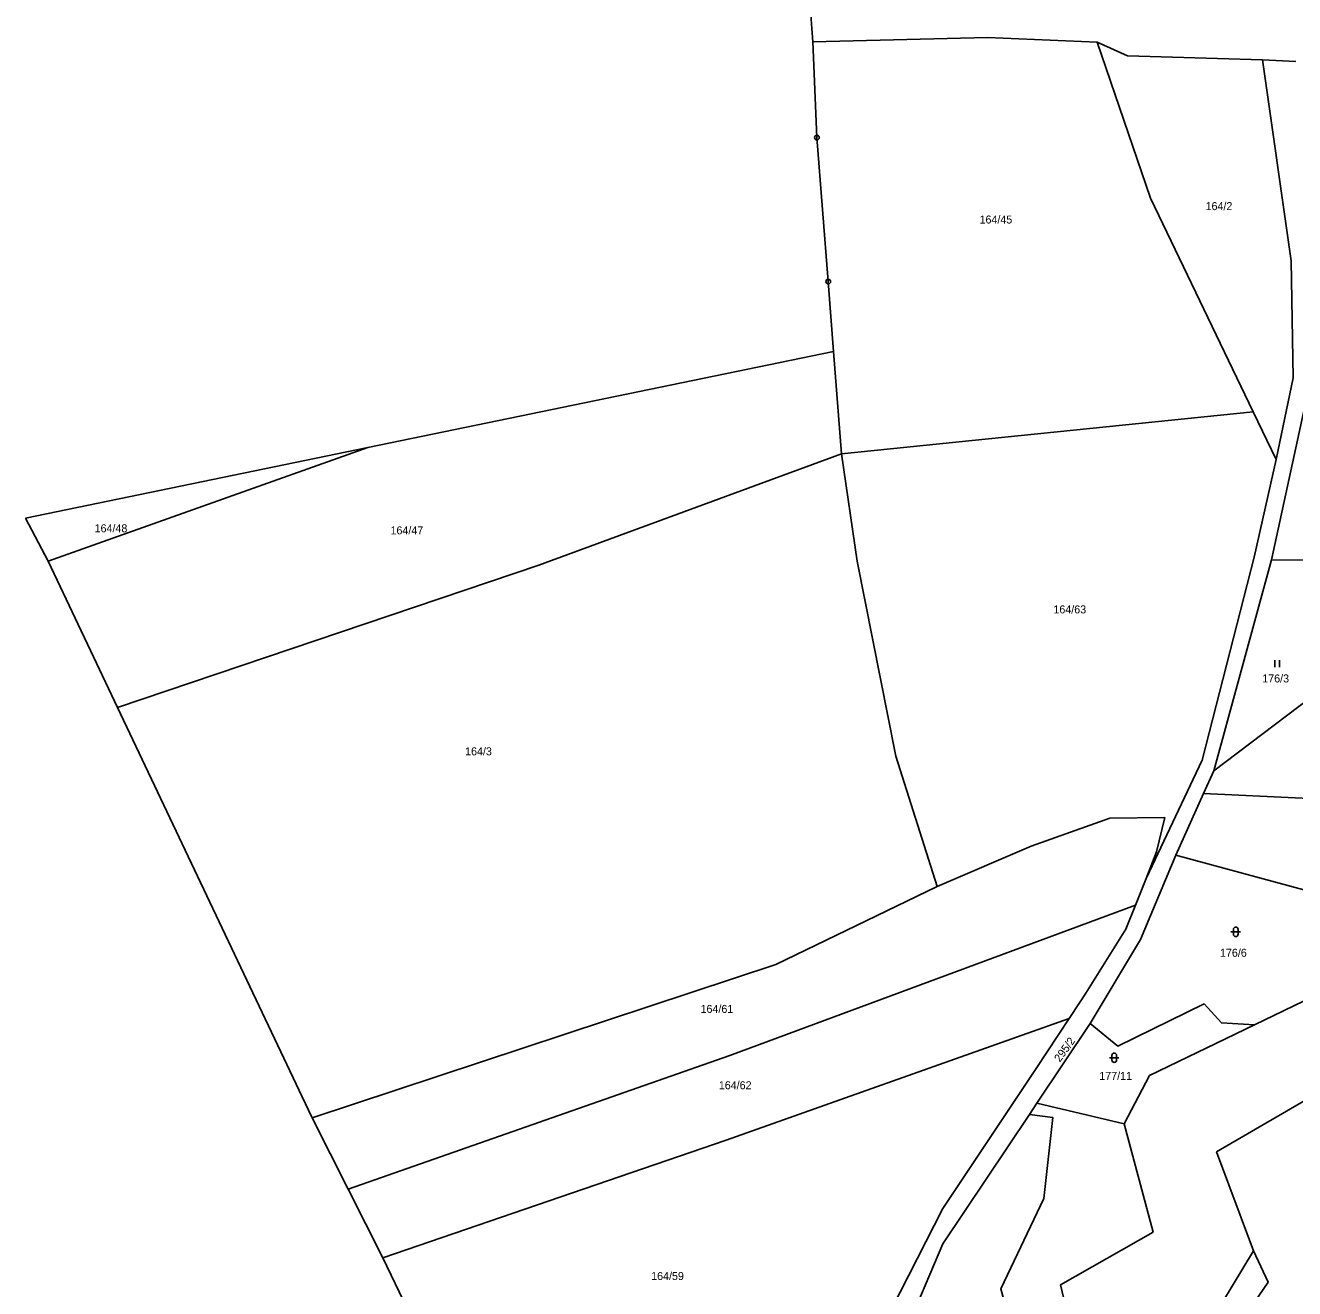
# Model space of a CAD drawing. Extents: x -779723 to -777378, y -1011169 to -1009297.
# Drawn here: x -779562.3 to -779292.8, y -1010743.9 to -1010475.7 of the extents above; entities that cross this region are included whole.
import ezdxf

# ---------------------------------------------------------------- set-up
doc = ezdxf.new("R2010")
doc.units = 0
for name, color, linetype in [('Hranice parcel', 7, 'Continuous'), ('Parcelní čísla', 7, 'Continuous'), ('Značky bodu BP', 7, 'Continuous'), ('Značky kultur', 7, 'Continuous')]:
    doc.layers.add(name, color=color, linetype=linetype)

msp = doc.modelspace()

# ---------------------------------------------------------------- linework, layer by layer
at = {"layer": 'Hranice parcel'}
for p, q in [((-779395.32, -1010476.34), (-779395.1, -1010479.15)), ((-779395.1, -1010479.15), (-779394.26, -1010499.5)), ((-779299.61, -1010483.03), (-779292.52, -1010483.32)), ((-779394.26, -1010499.5), (-779391.85, -1010530.1)), ((-779391.85, -1010530.1), (-779390.7, -1010544.93)), ((-779390.7, -1010544.93), (-779489.63, -1010565.32)), ((-779390.7, -1010544.93), (-779389.01, -1010566.7)), ((-779389.01, -1010566.7), (-779301.63, -1010557.72)), ((-779301.63, -1010557.72), (-779296.69, -1010567.88)), ((-779489.63, -1010565.32), (-779562.34, -1010580.31)), ((-779489.63, -1010565.32), (-779557.53, -1010589.43)), ((-779562.34, -1010580.31), (-779557.53, -1010589.43)), ((-779557.53, -1010589.43), (-779542.79, -1010620.51)), ((-779297.68, -1010589.2), (-779309.99, -1010633.95)), ((-779297.68, -1010589.2), (-779290.32, -1010589.28)), ((-779309.99, -1010633.95), (-779277.57, -1010609.48)), ((-779542.79, -1010620.51), (-779501.57, -1010707.41)), ((-779309.99, -1010633.95), (-779312.17, -1010638.8)), ((-779312.17, -1010638.8), (-779318.06, -1010651.91)), ((-779312.17, -1010638.8), (-779249.32, -1010641.76)), ((-779318.06, -1010651.91), (-779259.7, -1010667.71)), ((-779324.36, -1010656.85), (-779326.62, -1010662.54)), ((-779301.35, -1010687.91), (-779259.7, -1010667.71)), ((-779347.52, -1010704.57), (-779336.2, -1010687.64)), ((-779347.52, -1010704.57), (-779349.1, -1010706.93)), ((-779329.01, -1010708.95), (-779347.52, -1010704.57)), ((-779501.57, -1010707.41), (-779501.45, -1010707.65)), ((-779501.45, -1010707.65), (-779493.79, -1010722.84)), ((-779493.79, -1010722.84), (-779486.45, -1010737.42)), ((-779486.45, -1010737.42), (-779465.55, -1010780.39))]:
    msp.add_line(p, q, dxfattribs=at)
for points in [[(-779396.12, -1010466.31), (-779395.56, -1010473.38), (-779395.32, -1010476.34)], [(-779334.72, -1010479.27), (-779357.99, -1010478.29), (-779395.1, -1010479.15)], [(-779334.72, -1010479.27), (-779323.42, -1010512.4), (-779301.63, -1010557.72)], [(-779299.61, -1010483.03), (-779328.3, -1010482.13), (-779334.72, -1010479.27)], [(-779296.69, -1010567.88), (-779293.08, -1010550.56), (-779293.5, -1010525.69), (-779299.61, -1010483.03)], [(-779289.37, -1010526.33), (-779289.53, -1010551.4), (-779297.68, -1010589.2)], [(-779389.01, -1010566.7), (-779453.28, -1010590.34), (-779542.79, -1010620.51)], [(-779368.68, -1010658.56), (-779377.52, -1010630.85), (-779385.7, -1010589.44), (-779389.01, -1010566.7)], [(-779296.69, -1010567.88), (-779301.39, -1010588.58), (-779312.45, -1010631.73), (-779324.36, -1010656.85)], [(-779324.36, -1010656.85), (-779322.12, -1010651.21), (-779320.39, -1010643.9), (-779332.07, -1010644.04), (-779348.77, -1010649.95), (-779368.68, -1010658.56)], [(-779318.06, -1010651.91), (-779325.55, -1010669.8), (-779336.2, -1010687.64)], [(-779501.45, -1010707.65), (-779402.97, -1010675.13), (-779368.68, -1010658.56)], [(-779493.79, -1010722.84), (-779412.71, -1010694.4), (-779326.62, -1010662.54)], [(-779326.62, -1010662.54), (-779328.65, -1010667.63), (-779337.14, -1010681.17), (-779338.32, -1010683.01), (-779340.67, -1010686.56)], [(-779336.2, -1010687.64), (-779330.33, -1010692.44), (-779312.04, -1010683.48), (-779308.33, -1010687.51), (-779301.35, -1010687.91)], [(-779340.67, -1010686.56), (-779413.52, -1010712.43), (-779486.45, -1010737.42)], [(-779340.67, -1010686.56), (-779347.72, -1010697.18), (-779367.53, -1010726.93), (-779378.43, -1010748.27)], [(-779301.35, -1010687.91), (-779323.61, -1010698.7), (-779329.01, -1010708.95)], [(-779301.54, -1010735.91), (-779309.36, -1010714.92), (-779270.06, -1010692.04), (-779246.07, -1010725.76)], [(-779349.1, -1010706.93), (-779367.48, -1010734.41), (-779381.29, -1010767), (-779385.45, -1010795.17), (-779381.9, -1010841.31)], [(-779363.63, -1010864.32), (-779363.45, -1010862.67), (-779360.98, -1010851.45), (-779363.29, -1010823.74), (-779366.41, -1010815.3), (-779369.54, -1010792.66), (-779366.29, -1010780.62), (-779361.85, -1010776.79), (-779347.99, -1010770.65), (-779355.18, -1010743.98), (-779346.07, -1010724.81), (-779344.18, -1010707.57), (-779349.1, -1010706.93)], [(-779329.01, -1010708.95), (-779322.87, -1010731.97), (-779342.51, -1010743.15), (-779336.5, -1010768.5), (-779338.7, -1010774.59), (-779357.19, -1010780.24), (-779361.2, -1010791.83), (-779354.07, -1010819.32), (-779352.89, -1010843.6), (-779357.7, -1010861.97)], [(-779325.9, -1010758.14), (-779312.63, -1010754.3), (-779301.54, -1010735.91)], [(-779301.43, -1010755.73), (-779306.77, -1010754.81), (-779298.42, -1010742.54), (-779301.54, -1010735.91)]]:
    msp.add_lwpolyline(points, dxfattribs=at)
at = {"layer": 'Značky bodu BP'}
for centre, radius in [((-779394.26, -1010499.5), 0.5), ((-779394.26, -1010499.5), 0.0303), ((-779391.85, -1010530.1), 0.5), ((-779391.85, -1010530.1), 0.0303)]:
    msp.add_circle(centre, radius, dxfattribs=at)
at = {"layer": 'Značky kultur'}
for p, q in [((-779296.99, -1010611.97), (-779296.99, -1010610.47)), ((-779295.99, -1010611.97), (-779295.99, -1010610.47)), ((-779306.31, -1010668.17), (-779304.31, -1010668.17)), ((-779305.81, -1010667.67), (-779305.81, -1010668.67)), ((-779304.81, -1010668.67), (-779304.81, -1010667.67)), ((-779332.1, -1010694.9), (-779330.1, -1010694.9)), ((-779331.6, -1010694.4), (-779331.6, -1010695.4)), ((-779330.6, -1010695.4), (-779330.6, -1010694.4))]:
    msp.add_line(p, q, dxfattribs=at)
for centre, start, end in [((-779305.31, -1010667.67), 0, 180), ((-779305.31, -1010668.67), 180, 359.9879), ((-779331.1, -1010694.4), 0, 180), ((-779331.1, -1010695.4), 180, 359.9879)]:
    msp.add_arc(centre, 0.5, start, end, dxfattribs=at)

# ---------------------------------------------------------------- texts
at = {"layer": 'Parcelní čísla'}
for s, p in [('164/2', (-779311.71, -1010514.91)), ('164/45', (-779359.71, -1010517.76)), ('164/48', (-779547.64, -1010583.33)), ('164/47', (-779484.8, -1010583.77)), ('164/63', (-779344.02, -1010600.55)), ('176/3', (-779299.67, -1010615.21)), ('164/3', (-779468.96, -1010630.69)), ('176/6', (-779308.65, -1010673.47)), ('164/61', (-779418.96, -1010685.39)), ('177/11', (-779334.28, -1010699.6)), ('164/62', (-779415.08, -1010701.6)), ('164/59', (-779429.45, -1010742.11))]:
    msp.add_text(s, height=1.7, dxfattribs=at).set_placement(p)
msp.add_text('295/2', height=1.7, rotation=54, dxfattribs=at).set_placement((-779342.64, -1010695.95))

doc.saveas('drawing.dxf')
